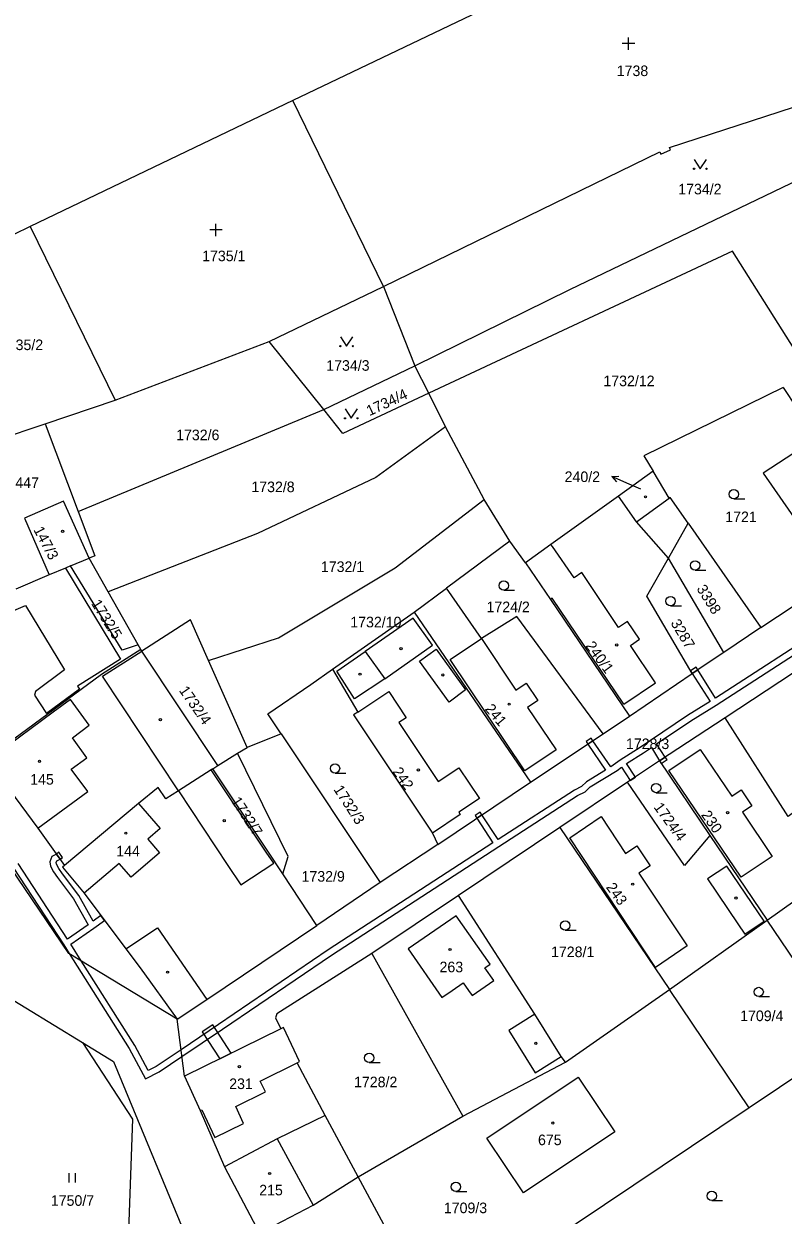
# Model space of a CAD drawing. Extents: x -776734 to -748832, y -1118122 to -976986.
# Drawn here: x -753163.9 to -753041.9, y -1116025.5 to -1115834 of the extents above; entities that cross this region are included whole.
import ezdxf

# ---------------------------------------------------------------- set-up
doc = ezdxf.new("R2010")
doc.units = 0
for name, color, linetype in [('KM_Hranice parcel', 7, 'Continuous'), ('KM_Parcelní čísla', 7, 'Continuous'), ('KM_Pop  PČ popisy', 7, 'Continuous'), ('KM_Vnitřní kresba', 7, 'Continuous'), ('KM_Věcná břemena k části', 7, 'Continuous'), ('KM_Značky budov', 7, 'Continuous'), ('KM_Značky kultur', 7, 'Continuous')]:
    doc.layers.add(name, color=color, linetype=linetype)

msp = doc.modelspace()

# ---------------------------------------------------------------- linework, layer by layer
at = {"layer": 'KM_Hranice parcel'}
for p, q in [((-753078.93, -1115826.31), (-753120.68, -1115846.33)), ((-753120.68, -1115846.33), (-753162.88, -1115866.54)), ((-753106.15, -1115876.19), (-753120.68, -1115846.33)), ((-753162.88, -1115866.54), (-753177.41, -1115873.66)), ((-753162.88, -1115866.54), (-753149.2, -1115894.45)), ((-753124.49, -1115885.02), (-753106.15, -1115876.19)), ((-753106.15, -1115876.19), (-753101.07, -1115888.95)), ((-753149.2, -1115894.45), (-753124.49, -1115885.02)), ((-753115.71, -1115895.98), (-753124.49, -1115885.02)), ((-753115.71, -1115895.98), (-753101.07, -1115888.95)), ((-753098.87, -1115893.36), (-753101.07, -1115888.95)), ((-753096.16, -1115898.78), (-753098.87, -1115893.36)), ((-753160.47, -1115898.27), (-753149.2, -1115894.45)), ((-753155.16, -1115912.35), (-753115.71, -1115895.98)), ((-753170.03, -1115901.51), (-753160.47, -1115898.27)), ((-753160.47, -1115898.27), (-753155.16, -1115912.35)), ((-753089.98, -1115910.42), (-753096.16, -1115898.78)), ((-753062.83, -1115905.88), (-753068.39, -1115909.88)), ((-753085.82, -1115917.11), (-753089.98, -1115910.42)), ((-753060.38, -1115919.85), (-753057.2, -1115914.24)), ((-753057.2, -1115914.24), (-753045.55, -1115930.99)), ((-753085.82, -1115917.11), (-753096.01, -1115924.7)), ((-753083.31, -1115920.61), (-753085.82, -1115917.11)), ((-753156.38, -1115921.11), (-753153.4, -1115919.88)), ((-753150.33, -1115925.3), (-753153.4, -1115919.88)), ((-753051.48, -1115935.01), (-753060.38, -1115919.85)), ((-753159.81, -1115922.53), (-753165.17, -1115924.86)), ((-753045.55, -1115930.99), (-753033.5, -1115923.04)), ((-753145.51, -1115933.78), (-753150.33, -1115925.3)), ((-753101.21, -1115928.57), (-753096.01, -1115924.7)), ((-753114.32, -1115937.71), (-753101.21, -1115928.57)), ((-753101.21, -1115928.57), (-753082.54, -1115955.89)), ((-753045.55, -1115930.99), (-753051.48, -1115935.01)), ((-753145.08, -1115934.55), (-753145.51, -1115933.78)), ((-753144.92, -1115934.8), (-753145.08, -1115934.55)), ((-753132.75, -1115953.2), (-753144.92, -1115934.8)), ((-753051.48, -1115935.01), (-753056.53, -1115938.43)), ((-753128.04, -1115950.28), (-753134.25, -1115936.29)), ((-753066.61, -1115945.27), (-753056.53, -1115938.43)), ((-753040.26, -1115938.31), (-753051.26, -1115945.53)), ((-753122.58, -1115948.1), (-753124.71, -1115944.9)), ((-753070.85, -1115948.1), (-753066.61, -1115945.27)), ((-753051.26, -1115945.53), (-753061.82, -1115952.46)), ((-753122.58, -1115948.1), (-753128.04, -1115950.28)), ((-753122.58, -1115948.1), (-753106.68, -1115972.01)), ((-753082.54, -1115955.89), (-753070.85, -1115948.1)), ((-753129.56, -1115951.22), (-753128.04, -1115950.28)), ((-753132.75, -1115953.2), (-753129.56, -1115951.22)), ((-753061.82, -1115952.46), (-753066.95, -1115955.89)), ((-753061.82, -1115952.46), (-753053.72, -1115964.44)), ((-753133.56, -1115953.71), (-753132.75, -1115953.2)), ((-753097.42, -1115965.87), (-753082.54, -1115955.89)), ((-753066.95, -1115955.89), (-753077.8, -1115963.14)), ((-753077.8, -1115963.14), (-753094.1, -1115974.09)), ((-753077.8, -1115963.14), (-753060.22, -1115989.18)), ((-753097.42, -1115965.87), (-753106.68, -1115972.01)), ((-753053.72, -1115964.44), (-753044.53, -1115978.04)), ((-753044.53, -1115978.04), (-753028.67, -1115966.79)), ((-753116.82, -1115978.9), (-753122.28, -1115970.59)), ((-753106.68, -1115972.01), (-753116.82, -1115978.9)), ((-753094.1, -1115974.09), (-753108, -1115983.43)), ((-753060.22, -1115989.18), (-753044.53, -1115978.04)), ((-753031.39, -1115997.48), (-753044.53, -1115978.04)), ((-753179.85, -1115982.22), (-753154.47, -1115997.72)), ((-753108, -1115983.43), (-753093.39, -1116009.57)), ((-753076.91, -1116000.86), (-753060.22, -1115989.18)), ((-753047.38, -1116008.2), (-753060.22, -1115989.18)), ((-753138.09, -1116003.11), (-753139.27, -1115993.97)), ((-753122.59, -1115995.5), (-753138.09, -1116003.11)), ((-753031.39, -1115997.48), (-753047.38, -1116008.2)), ((-753093.39, -1116009.57), (-753076.91, -1116000.86)), ((-753110.2, -1116019.29), (-753115.47, -1116009.44)), ((-753110.2, -1116019.29), (-753093.39, -1116009.57)), ((-753131.67, -1116017.69), (-753126.03, -1116028.34)), ((-753101.59, -1116035.19), (-753110.2, -1116019.29))]:
    msp.add_line(p, q, dxfattribs=at)
for points in [[(-753106.15, -1115876.19), (-753061.76, -1115854.55), (-753061.59, -1115854.94), (-753060.04, -1115854.25), (-753060.21, -1115853.86), (-753015.93, -1115839.43)], [(-753101.07, -1115888.95), (-753076.21, -1115876.67), (-753037.99, -1115858.31), (-753008.35, -1115847.01)], [(-753037.6, -1115890.31), (-753050.08, -1115870.52), (-753098.87, -1115893.36)], [(-753098.87, -1115893.36), (-753112.64, -1115899.81), (-753115.71, -1115895.98)], [(-753041.92, -1115892.42), (-753064.31, -1115903.41), (-753062.83, -1115905.88)], [(-753041.92, -1115892.42), (-753039.75, -1115895.76), (-753036.39, -1115900.5), (-753045.16, -1115906.22), (-753033.5, -1115923.04)], [(-753096.16, -1115898.78), (-753107.36, -1115906.9), (-753126.35, -1115915.92), (-753150.33, -1115925.3)], [(-753057.2, -1115914.24), (-753060.07, -1115910.13), (-753060.24, -1115910.23), (-753062.83, -1115905.88)], [(-753134.25, -1115936.29), (-753122.99, -1115932.66), (-753104.27, -1115921.44), (-753089.98, -1115910.42)], [(-753068.39, -1115909.88), (-753079.23, -1115917.68), (-753083.31, -1115920.61)], [(-753060.38, -1115919.85), (-753065.5, -1115914.02), (-753068.39, -1115909.88)], [(-753153.4, -1115919.88), (-753157.54, -1115910.69), (-753163.79, -1115913.42), (-753159.81, -1115922.53)], [(-753155.16, -1115912.35), (-753152.47, -1115919.5), (-753153.4, -1115919.88)], [(-753056.53, -1115938.43), (-753063.86, -1115925.97), (-753060.38, -1115919.85)], [(-753156.38, -1115921.11), (-753157.19, -1115921.45), (-753159.81, -1115922.53)], [(-753145.51, -1115933.78), (-753148.11, -1115934.64), (-753156.38, -1115921.11)], [(-753083.31, -1115920.61), (-753079.31, -1115926.52), (-753066.61, -1115945.27)], [(-753070.85, -1115948.1), (-753084.74, -1115929.26), (-753090.4, -1115932.8), (-753096.01, -1115924.7)], [(-753134.25, -1115936.29), (-753137.14, -1115929.78), (-753144.92, -1115934.8)], [(-753145.08, -1115934.55), (-753151.42, -1115938.56), (-753169.85, -1115952.13)], [(-753124.71, -1115944.9), (-753117.82, -1115940.15), (-753114.32, -1115937.71)], [(-753114.32, -1115937.71), (-753110.24, -1115944.6), (-753110.95, -1115945.07), (-753098.28, -1115964.04), (-753097.42, -1115965.87)], [(-753028.67, -1115966.79), (-753036.7, -1115958.02), (-753041.16, -1115961.4), (-753051.26, -1115945.53)], [(-753139.27, -1115993.97), (-753156.66, -1115983.38), (-753171.95, -1115960.83), (-753180.64, -1115948.4)], [(-753169.85, -1115952.13), (-753169.71, -1115952.39), (-753161.66, -1115963.27), (-753157.34, -1115969.26)], [(-753122.28, -1115970.59), (-753121.46, -1115967.79), (-753129.56, -1115951.22)], [(-753133.56, -1115953.71), (-753133.81, -1115953.87), (-753139.07, -1115957.24), (-753141.06, -1115958.55), (-753142.34, -1115956.7), (-753145.45, -1115959.3), (-753157.34, -1115969.26)], [(-753122.28, -1115970.59), (-753124.69, -1115966.94), (-753133.56, -1115953.71)], [(-753053.72, -1115964.44), (-753057.77, -1115969.26), (-753066.95, -1115955.89)], [(-753157.34, -1115969.26), (-753157.68, -1115969.54), (-753154.2, -1115973.72), (-753147.52, -1115982.63), (-753145.23, -1115985.69), (-753139.27, -1115993.97)], [(-753076.91, -1116000.86), (-753077.59, -1115999.96), (-753081.85, -1115993.18), (-753094.1, -1115974.09)], [(-753139.27, -1115993.97), (-753134.48, -1115990.81), (-753116.82, -1115978.9)], [(-753108, -1115983.43), (-753123.25, -1115993.11), (-753123.47, -1115993.74), (-753122.59, -1115995.5)], [(-753115.47, -1116009.44), (-753120.02, -1116000.98), (-753119.62, -1116000.78), (-753122.19, -1115995.3), (-753122.59, -1115995.5)], [(-753154.47, -1115997.72), (-753149.49, -1116000.76), (-753136.36, -1116032.48), (-753120.16, -1116066.32)], [(-753154.47, -1115997.72), (-753146.44, -1116010.01), (-753148.15, -1116057.97), (-753149.75, -1116066.6), (-753152.14, -1116079.47)], [(-753138.09, -1116003.11), (-753135.55, -1116008.65), (-753131.67, -1116017.69)], [(-753089.52, -1116013.08), (-753074.86, -1116003.27), (-753068.97, -1116012.08), (-753083.63, -1116021.87), (-753089.52, -1116013.08)], [(-753047.38, -1116008.2), (-753079.92, -1116030), (-753098.72, -1116040.49)], [(-753115.47, -1116009.44), (-753123.22, -1116013.21), (-753131.67, -1116017.69)], [(-753126.03, -1116028.34), (-753117.45, -1116023.84), (-753110.2, -1116019.29)]]:
    msp.add_lwpolyline(points, dxfattribs=at)
at = {"layer": 'KM_Pop  PČ popisy'}
for p, q in [((-753069.432, -1115906.759), (-753068.313, -1115906.709)), ((-753066.69, -1115907.98), (-753069.432, -1115906.759)), ((-753069.432, -1115906.759), (-753068.72, -1115907.624)), ((-753064.81, -1115908.8), (-753066.69, -1115907.98))]:
    msp.add_line(p, q, dxfattribs=at)
at = {"layer": 'KM_Vnitřní kresba'}
for p, q in [((-753065.5, -1115914.02), (-753060.24, -1115910.23)), ((-753079, -1115918), (-753079.23, -1115917.68)), ((-753075.52, -1115923.02), (-753079, -1115918)), ((-753157.19, -1115921.45), (-753148.35, -1115936.11)), ((-753074.28, -1115922.19), (-753075.52, -1115923.02)), ((-753068.39, -1115931.02), (-753074.28, -1115922.19)), ((-753170.6, -1115930.48), (-753163.61, -1115927.45)), ((-753163.61, -1115927.45), (-753157.34, -1115937.8)), ((-753079.02, -1115926.32), (-753079.31, -1115926.52)), ((-753067.54, -1115943.33), (-753079.02, -1115926.32)), ((-753101.35, -1115929.5), (-753109.07, -1115934.86)), ((-753098.28, -1115933.84), (-753101.35, -1115929.5)), ((-753066.93, -1115930.05), (-753068.39, -1115931.02)), ((-753065.02, -1115932.91), (-753066.93, -1115930.05)), ((-753095.42, -1115936.18), (-753090.4, -1115932.8)), ((-753090.4, -1115932.8), (-753084.85, -1115941.07)), ((-753066.48, -1115933.88), (-753065.02, -1115932.91)), ((-753151.25, -1115938.81), (-753144.92, -1115934.8)), ((-753113.63, -1115938.04), (-753109.07, -1115934.86)), ((-753109.07, -1115934.86), (-753105.91, -1115939.25)), ((-753105.91, -1115939.25), (-753098.28, -1115933.84)), ((-753100.37, -1115936.41), (-753097.68, -1115934.47)), ((-753097.68, -1115934.47), (-753092.97, -1115941.05)), ((-753062.45, -1115939.92), (-753066.48, -1115933.88)), ((-753148.35, -1115936.11), (-753155.26, -1115940.45)), ((-753095.59, -1115943.01), (-753100.37, -1115936.41)), ((-753083.44, -1115954.05), (-753095.42, -1115936.18)), ((-753157.34, -1115937.8), (-753162.04, -1115941.32)), ((-753139.07, -1115957.24), (-753151.25, -1115938.81)), ((-753110.79, -1115942.47), (-753113.63, -1115938.04)), ((-753105.91, -1115939.25), (-753110.79, -1115942.47)), ((-753162.04, -1115941.32), (-753162.17, -1115941.88)), ((-753154.97, -1115940.91), (-753160.27, -1115944.84)), ((-753155.26, -1115940.45), (-753154.97, -1115940.91)), ((-753110.24, -1115944.6), (-753105.29, -1115941.3)), ((-753105.29, -1115941.3), (-753102.48, -1115945.51)), ((-753092.97, -1115941.05), (-753095.59, -1115943.01)), ((-753084.85, -1115941.07), (-753083.19, -1115939.96)), ((-753083.19, -1115939.96), (-753081.33, -1115942.74)), ((-753067.54, -1115943.33), (-753062.45, -1115939.92)), ((-753162.17, -1115941.88), (-753160.27, -1115944.84)), ((-753156.41, -1115942.61), (-753159.17, -1115944.64)), ((-753153.4, -1115946.73), (-753156.41, -1115942.61)), ((-753081.33, -1115942.74), (-753082.99, -1115943.85)), ((-753159.17, -1115944.64), (-753169.71, -1115952.39)), ((-753082.99, -1115943.85), (-753078.41, -1115950.67)), ((-753156.07, -1115948.74), (-753153.4, -1115946.73)), ((-753102.48, -1115945.51), (-753103.66, -1115946.3)), ((-753103.66, -1115946.3), (-753097.35, -1115955.77)), ((-753153.75, -1115951.95), (-753156.07, -1115948.74)), ((-753078.41, -1115950.67), (-753083.44, -1115954.05)), ((-753060.28, -1115954.02), (-753055.25, -1115950.62)), ((-753055.25, -1115950.62), (-753050.2, -1115958.12)), ((-753156.28, -1115953.78), (-753153.75, -1115951.95)), ((-753153.61, -1115957.38), (-753156.28, -1115953.78)), ((-753125.92, -1115965.66), (-753133.81, -1115953.87)), ((-753097.35, -1115955.77), (-753094.04, -1115953.58)), ((-753094.04, -1115953.58), (-753090.72, -1115958.48)), ((-753048.66, -1115971.13), (-753060.28, -1115954.02)), ((-753161.66, -1115963.27), (-753153.61, -1115957.38)), ((-753139.07, -1115957.24), (-753131.14, -1115969.24)), ((-753090.72, -1115958.48), (-753094.04, -1115960.69)), ((-753050.2, -1115958.12), (-753048.7, -1115957.12)), ((-753048.7, -1115957.12), (-753046.99, -1115959.66)), ((-753145.45, -1115959.3), (-753141.97, -1115963.29)), ((-753046.99, -1115959.66), (-753048.49, -1115960.67)), ((-753093.79, -1115961.05), (-753098.28, -1115964.04)), ((-753094.04, -1115960.69), (-753093.79, -1115961.05)), ((-753076.22, -1115964.81), (-753071.19, -1115961.4)), ((-753071.19, -1115961.4), (-753067.24, -1115967.32)), ((-753048.49, -1115960.67), (-753043.7, -1115967.79)), ((-753141.97, -1115963.29), (-753143.99, -1115965.01)), ((-753143.99, -1115965.01), (-753142.08, -1115967.25)), ((-753124.95, -1115967.11), (-753125.92, -1115965.66)), ((-753062.42, -1115985.66), (-753076.22, -1115964.81)), ((-753067.24, -1115967.32), (-753065.42, -1115966.1)), ((-753065.42, -1115966.1), (-753063.28, -1115969.3)), ((-753142.08, -1115967.25), (-753146.67, -1115971.15)), ((-753123.75, -1115968.9), (-753124.95, -1115967.11)), ((-753043.7, -1115967.79), (-753048.66, -1115971.13)), ((-753148.57, -1115968.92), (-753154.2, -1115973.72)), ((-753146.67, -1115971.15), (-753148.57, -1115968.92)), ((-753131.14, -1115969.24), (-753129.06, -1115972.37)), ((-753129.06, -1115972.37), (-753123.75, -1115968.9)), ((-753063.28, -1115969.3), (-753065.11, -1115970.52)), ((-753051.01, -1115969.36), (-753054.07, -1115971.43)), ((-753044.99, -1115978.21), (-753051.01, -1115969.36)), ((-753065.11, -1115970.52), (-753057.34, -1115982.15)), ((-753054.07, -1115971.43), (-753049.24, -1115978.64)), ((-753094.45, -1115977.36), (-753102.15, -1115982.67)), ((-753089.02, -1115985.14), (-753094.45, -1115977.36)), ((-753147.52, -1115982.63), (-753142.41, -1115979.26)), ((-753142.41, -1115979.26), (-753134.48, -1115990.81)), ((-753049.24, -1115978.64), (-753048.12, -1115980.31)), ((-753048.12, -1115980.31), (-753044.99, -1115978.21)), ((-753102.15, -1115982.67), (-753096.75, -1115990.48)), ((-753057.34, -1115982.15), (-753062.42, -1115985.66)), ((-753089.84, -1115985.71), (-753089.02, -1115985.14)), ((-753088.42, -1115987.76), (-753089.84, -1115985.71)), ((-753095.1, -1115989.35), (-753093.34, -1115988.12)), ((-753093.34, -1115988.12), (-753092.48, -1115989.36)), ((-753091.91, -1115990.18), (-753088.42, -1115987.76)), ((-753096.75, -1115990.48), (-753095.1, -1115989.35)), ((-753092.48, -1115989.36), (-753091.91, -1115990.18)), ((-753081.85, -1115993.18), (-753086.01, -1115995.79)), ((-753086.01, -1115995.79), (-753081.75, -1116002.57)), ((-753081.75, -1116002.57), (-753077.59, -1115999.96)), ((-753125.95, -1116003.91), (-753120.02, -1116000.98)), ((-753125.1, -1116005.63), (-753125.95, -1116003.91)), ((-753129.86, -1116007.98), (-753125.1, -1116005.63)), ((-753128.63, -1116010.74), (-753129.86, -1116007.98)), ((-753135.55, -1116008.65), (-753135.28, -1116008.53)), ((-753135.28, -1116008.53), (-753133.2, -1116012.99)), ((-753133.2, -1116012.99), (-753128.63, -1116010.74)), ((-753123.22, -1116013.21), (-753117.45, -1116023.84))]:
    msp.add_line(p, q, dxfattribs=at)
at = {"layer": 'KM_Věcná břemena k části'}
for points in [[(-753131.96, -1115995.58), (-753114.48, -1115983.7), (-753087.59, -1115966.21), (-753074.96, -1115958.01), (-753073.76, -1115957.42), (-753072.92, -1115956.62), (-753068.61, -1115953.98), (-753067.93, -1115953.46), (-753066.51, -1115955.59), (-753065.68, -1115955.04), (-753067.12, -1115952.89), (-753064.35, -1115951.16), (-753063.09, -1115950.28), (-753061.82, -1115952.46), (-753060.87, -1115951.83), (-753062.27, -1115949.72), (-753056.76, -1115945.99), (-753052.72, -1115943.49), (-753033.91, -1115931.33)], [(-753034.46, -1115930.49), (-753052.83, -1115942.38), (-753055.65, -1115937.83), (-753056.53, -1115938.43), (-753053.68, -1115942.91), (-753057.31, -1115945.15), (-753063.25, -1115949.17), (-753064.9, -1115950.32), (-753068.1, -1115952.33), (-753069.63, -1115953.41), (-753072.49, -1115949.2), (-753073.32, -1115949.75), (-753070.48, -1115953.93), (-753073.52, -1115955.82), (-753074.34, -1115956.58), (-753075.45, -1115957.13), (-753087.72, -1115965.1), (-753090.31, -1115961.1)], [(-753090.31, -1115961.1), (-753091.14, -1115961.66), (-753088.55, -1115965.64), (-753114.99, -1115982.83), (-753132.61, -1115994.81), (-753138.64, -1115998.87), (-753142.64, -1116001.57), (-753143.93, -1116002.22), (-753146.09, -1115998.17), (-753154.67, -1115984.59), (-753156.35, -1115981.93), (-753152.66, -1115979.36), (-753150.93, -1115978.08), (-753151.53, -1115977.28), (-753152.77, -1115978.2), (-753155.07, -1115974.09), (-753157.69, -1115970.6), (-753158.29, -1115969.74), (-753158.66, -1115969.05), (-753158.7, -1115968.77), (-753158.61, -1115968.53), (-753158.07, -1115968.25), (-753158.66, -1115967.43), (-753159.41, -1115967.81), (-753159.72, -1115968.65), (-753159.62, -1115969.37), (-753159.14, -1115970.27), (-753158.5, -1115971.19), (-753155.91, -1115974.64), (-753153.58, -1115978.79), (-753156.9, -1115981.08), (-753164.82, -1115968.96)], [(-753169.02, -1115971.1), (-753166.33, -1115969.12), (-753166.2, -1115969.03), (-753165.6, -1115969.6), (-753157.47, -1115982.03), (-753156.59, -1115983.42), (-753146.95, -1115998.69), (-753144.35, -1116003.56), (-753142.13, -1116002.43), (-753138.49, -1115999.98), (-753131.96, -1115995.58)]]:
    msp.add_lwpolyline(points, dxfattribs=at)
for points in [[(-753056.53, -1115938.43), (-753055.65, -1115937.83), (-753055.91, -1115937.41), (-753056.81, -1115937.95)], [(-753073.32, -1115949.75), (-753072.49, -1115949.2), (-753072.77, -1115948.79), (-753073.6, -1115949.34)], [(-753060.87, -1115951.83), (-753061.82, -1115952.46), (-753061.54, -1115952.88), (-753060.59, -1115952.25)], [(-753091.14, -1115961.66), (-753090.31, -1115961.1), (-753090.58, -1115960.68), (-753091.41, -1115961.24)], [(-753158.66, -1115967.43), (-753158.07, -1115968.25), (-753157.66, -1115967.96), (-753158.26, -1115967.14)], [(-753132.43, -1116000.33), (-753130.62, -1115999.44), (-753133.56, -1115994.89), (-753135.24, -1115995.97)]]:
    msp.add_lwpolyline(points, close=True, dxfattribs=at)
at = {"layer": 'KM_Značky budov'}
for centre in [(-753064.0468, -1115910.0192), (-753157.6568, -1115915.5492), (-753068.6768, -1115933.8192), (-753103.3168, -1115934.4192), (-753109.8968, -1115938.5192), (-753096.5968, -1115938.6392), (-753085.9368, -1115943.3392), (-753141.9668, -1115945.8292), (-753161.3668, -1115952.5192), (-753100.5268, -1115953.9092), (-753131.7068, -1115962.0692), (-753050.8668, -1115960.7592), (-753147.5168, -1115964.0692), (-753066.1068, -1115972.2692), (-753049.5268, -1115974.4892), (-753095.4368, -1115982.7592), (-753140.8068, -1115986.4092), (-753081.6568, -1115997.8392), (-753129.2768, -1116001.5892), (-753078.9268, -1116010.6592), (-753124.4168, -1116018.7592)]:
    msp.add_circle(centre, 0.175, dxfattribs=at)
at = {"layer": 'KM_Značky kultur'}
for p, q in [((-753065.779, -1115837.171), (-753067.781, -1115837.171)), ((-753066.78, -1115838.17), (-753066.78, -1115836.17)), ((-753133.04, -1115868.11), (-753133.04, -1115866.11)), ((-753132.039, -1115867.111), (-753134.041, -1115867.111)), ((-753049.873, -1115910.34), (-753048.123, -1115910.34)), ((-753056.093, -1115921.78), (-753054.343, -1115921.78)), ((-753086.813, -1115925.03), (-753085.063, -1115925.03)), ((-753060.023, -1115927.51), (-753058.273, -1115927.51)), ((-753113.913, -1115954.42), (-753112.163, -1115954.42)), ((-753062.343, -1115957.56), (-753060.593, -1115957.56)), ((-753076.933, -1115979.66), (-753075.183, -1115979.66)), ((-753045.873, -1115990.34), (-753044.123, -1115990.34)), ((-753108.413, -1116000.94), (-753106.663, -1116000.94)), ((-753156.611, -1116020.22), (-753156.611, -1116018.72)), ((-753155.61, -1116020.22), (-753155.61, -1116018.72)), ((-753094.493, -1116021.66), (-753092.743, -1116021.66)), ((-753053.413, -1116023.12), (-753051.663, -1116023.12))]:
    msp.add_line(p, q, dxfattribs=at)
for points in [[(-753056.25, -1115855.779), (-753055.25, -1115857.28), (-753054.25, -1115855.779)], [(-753113.05, -1115884.289), (-753112.05, -1115885.79), (-753111.05, -1115884.289)], [(-753112.31, -1115895.889), (-753111.31, -1115897.39), (-753110.31, -1115895.889)]]:
    msp.add_lwpolyline(points, dxfattribs=at)
for centre, radius in [((-753056.25, -1115857.2795), 0.1), ((-753054.25, -1115857.2795), 0.1), ((-753113.05, -1115885.7895), 0.1), ((-753111.05, -1115885.7895), 0.1), ((-753112.31, -1115897.3895), 0.1), ((-753110.31, -1115897.3895), 0.1), ((-753049.8729, -1115909.5898), 0.75), ((-753056.0929, -1115921.0298), 0.75), ((-753086.8129, -1115924.2798), 0.75), ((-753060.0229, -1115926.7598), 0.75), ((-753113.9129, -1115953.6698), 0.75), ((-753062.3429, -1115956.8098), 0.75), ((-753076.9329, -1115978.9098), 0.75), ((-753045.8729, -1115989.5898), 0.75), ((-753108.4129, -1116000.1898), 0.75), ((-753094.4929, -1116020.9098), 0.75), ((-753053.4129, -1116022.3698), 0.75)]:
    msp.add_circle(centre, radius, dxfattribs=at)

# ---------------------------------------------------------------- texts
at = {"layer": 'KM_Parcelní čísla'}
for s, p in [('1738', (-753068.67, -1115842.39)), ('1734/2', (-753058.79, -1115861.4)), ('1735/1', (-753135.25, -1115872.14)), ('1735/2', (-753167.74, -1115886.43)), ('1734/3', (-753115.32, -1115889.75)), ('1732/12', (-753070.81, -1115892.23)), ('1732/6', (-753139.43, -1115900.91)), ('3447', (-753166.514, -1115908.58)), ('240/2', (-753077.037, -1115907.63)), ('1732/8', (-753127.35, -1115909.26)), ('1721', (-753051.24, -1115914.08)), ('1732/1', (-753116.18, -1115922.09)), ('1724/2', (-753089.58, -1115928.55)), ('1732/10', (-753111.46, -1115930.99)), ('1728/3', (-753067.19, -1115950.55)), ('145', (-753162.87, -1115956.27)), ('144', (-753149.05, -1115967.8)), ('1732/9', (-753119.29, -1115971.86)), ('1728/1', (-753079.22, -1115983.99)), ('263', (-753097.13, -1115986.42)), ('1709/4', (-753048.85, -1115994.27)), ('231', (-753130.91, -1116005.19)), ('1728/2', (-753110.86, -1116004.91)), ('675', (-753081.315, -1116014.21)), ('215', (-753126.09, -1116022.28)), ('1750/7', (-753159.55, -1116023.96)), ('1709/3', (-753096.437, -1116025.14))]:
    msp.add_text(s, height=1.7, dxfattribs=at).set_placement(p)
for s, rotation, p in [('1734/4', 25, (-753108.39, -1115897.06)), ('147/3', 298, (-753162.39, -1115915.299)), ('3398', 302, (-753055.91, -1115924.78)), ('1732/5', 302, (-753153.13, -1115927.16)), ('3287', 301, (-753060.078, -1115930.297)), ('240/1', 306, (-753073.757, -1115933.969)), ('1732/4', 305, (-753139.046, -1115941.127)), ('241', 310, (-753089.931, -1115944.146)), ('242', 305, (-753104.746, -1115954.187)), ('1732/3', 303, (-753114.222, -1115957.022)), ('1732/7', 303, (-753130.662, -1115958.892)), ('1724/4', 306, (-753062.807, -1115959.899)), ('230', 305, (-753055.186, -1115961.137)), ('243', 306, (-753070.467, -1115972.769))]:
    msp.add_text(s, height=1.7, rotation=rotation, dxfattribs=at).set_placement(p)

doc.saveas('drawing.dxf')
